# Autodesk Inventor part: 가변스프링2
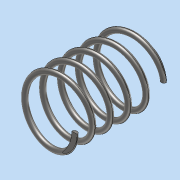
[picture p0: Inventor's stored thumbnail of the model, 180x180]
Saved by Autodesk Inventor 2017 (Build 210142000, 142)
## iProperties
Part Number: 가변스프링2
Material: 강철, 연강
Document SubType Name: Modeling
Designer: MRC
Density: 7.85 g/cm^3
Appearance: 반연마
Mass: 8.41507 g
Surface Area: 21.7061 cm^2
Volume: 1.07198 cm^3
Author: MRC
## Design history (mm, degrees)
sketch "스케치1"
  geometry: L1 (0, 0)-(0, -33.727); L2 (0, 0)-(11, 0); L3 (0, -33.727)-(11.069, -33.727); C1 r 1 at (11, 0)
  constraints: 6 end point, 2 horizontal, 1 centre point, 1 coincident, 1 vertical
  dimensions: "d1" = 22 diameter of L2.end L1; "d2" = 2 diameter of C1; "d4" = 33.7269 distance of L1.start L1.end (derived)
feature "코일1" sketch "스케치1" pitch "d5" = 10; turns "d7" = 5; dims "d6" = 33.7269 (= d4), "d8" = 0, angle "d9" = 90 deg, angle "d10" = 90 deg, "d11" = 0, "d12" = 0
sketch "스케치2"
  geometry: L1 (0, 18.659)-(-33.727, 18.659); L2 (-33.727, 18.659)-(-33.727, -18.118); L3 (-33.727, -18.118)-(0, -18.118); L4 (0, -18.118)-(0, 18.659); 1 further point
  constraints: 8 end point, 2 parallel, 1 horizontal, 1 perpendicular, 1 point on line
  dimensions: "d17" = 33.7269 distance of L2.end L3.end (= d4)
extrude "돌출1" sketch "스케치2" stored distance "d15" = 30; taper "d16" = 0 deg
node "솔리드1"
